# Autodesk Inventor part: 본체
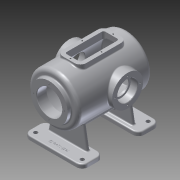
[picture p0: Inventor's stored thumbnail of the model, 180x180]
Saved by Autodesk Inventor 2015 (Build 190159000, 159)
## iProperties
Created: 2016-02
Part Number: 본체
Material: 알루미늄 6061
Document SubType Name: Modeling
Designer: mduedu
Density: 2.71 g/cm^3
Appearance: 알루미늄 - 평지
Author: mduedu
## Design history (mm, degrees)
sketch "스케치2"
  geometry: L1 (0, 100)-(0, -100); L2 (65, -87.083)-(65, 100); L3 (65, 100)-(0, 100); A1 r 170 centre (0, 70) between (0, -100) and (65, -87.083); 2 further points
  constraints: 6 end point, 2 point on circle, 1 centre point, 1 coincident, 1 horizontal, 1 midpoint, 1 parallel, 1 point on line, 1 vertical
  dimensions: "d3" = 200 distance of L1.start L1.end; "d5" = 130 diameter of L2 L1; "d6" = 170 radius of A1
revolve "회전1" sketch "스케치2" stored, may be unused: angle "d7" = 90 deg
sketch "스케치3"
  geometry: C1 r 47.5 at (0, 0); 1 further point
  constraints: 1 centre point, 1 coincident
  dimensions: "d8" = 95 diameter of C1
extrude "돌출2" join sketch "스케치3" distance "d10" = 10; taper "d11" = 0 deg
sketch "스케치5"
  geometry: L1 (47.5, 110)-(47.5, 100) reference; L2 (47.5, 100)-(65, 100) reference; L3 (65, 100)-(65, -87.083) reference; L4 (-65, -87.083)-(-65, 100) reference; L5 (-65, 100)-(-47.5, 100) reference; L6 (-47.5, 100)-(-47.5, 110) reference; L7 (-47.5, 110)-(47.5, 110) reference; L8 (55, 85)-(55, -80.25); L9 (0, 85)-(55, 85); L10 (0, 85)-(0, -90); A1 r 170 centre (0, 70) between (-65, -87.083) and (0, -100) reference; A2 r 170 centre (0, 70) between (0, -100) and (65, -87.083) reference; A3 r 160 centre (0, 70) between (0, -90) and (55, -80.25); 1 further point
  constraints: 6 end point, 2 point on circle, 1 centre point, 1 parallel, 1 perpendicular, 1 point on line, 1 vertical
  dimensions: "d13" = 10 distance between parallel lines of L3 L8; "d14" = 10 radial gap between concentric circles of A3 A1; "d15" = 15 distance between parallel lines of L9 L2
revolve "회전2" sketch "스케치5" stored, may be unused: angle "d16" = 90 deg
hole "구멍1" diameter "d19" = 65; stored, may be unused: countersink angle "d23" = 90 deg, drill point angle "d25" = 118 deg; dims "d17" = 10, "d18" = 10, "d20" = 6, "d21" = 4, "d22" = 2, "d24" = 8
node "작업 평면1"
sketch "스케치6"
  geometry: L1 (47.5, 110)-(-47.5, 110) reference; C1 r 40 at (0, -17); 1 further point
  constraints: 1 centre point, 1 vertical alignment
  dimensions: "d27" = 80 diameter of C1; "d29" = 127 distance from line of C1.centre L1
extrude "돌출3" join sketch "스케치6" stored distance "d30" = 10; taper "d31" = 0 deg
hole "구멍2" diameter "d34" = 42; stored, may be unused: countersink angle "d38" = 90 deg, drill point angle "d40" = 118 deg; dims "d32" = 10, "d33" = 10, "d35" = 6, "d36" = 52, "d37" = 18, "d39" = 8
sketch "스케치7" dims "d41" = 65
  geometry: C1 r 40 at (0, 0) reference; 3 further points
  constraints: 2 vertical alignment, 1 coincident, 2 other
hole "구멍3" sketch "스케치7" at (0, 32.5) diameter "d43" = 3.242; stored, may be unused: countersink angle "d47" = 90 deg, drill point angle "d49" = 118 deg; dims "d44" = 11, "d45" = 13, "d46" = 18, "d48" = 13
sketch "스케치8" dims "d53" = 80
  geometry: 3 further points
  constraints: 2 vertical alignment, 1 coincident, 2 other
hole "구멍4" sketch "스케치8" at (0, 40) diameter "d56" = 3.242; stored, may be unused: countersink angle "d60" = 90 deg, drill point angle "d62" = 118 deg; dims "d57" = 11, "d58" = 13, "d59" = 18, "d61" = 13
fillet "모깎기1" dims "d66" = 10
fillet "모깎기2" dims "d67" = 3
fillet "모깎기3" dims "d68" = 0.3
chamfer "모따기1" distance "d69" = 1; stored, may be unused: second distance "d70" = 2, angle "d71" = 45 deg
node "작업 평면2"
sketch "스케치9"
  geometry: L1 (75, 100)-(-75, 100); L2 (-75, 100)-(-75, -100); L3 (-75, -100)-(75, -100); L4 (75, -100)-(75, 100); 1 further point
  constraints: 8 end point, 2 parallel, 1 horizontal, 1 perpendicular
  dimensions: "d73" = 200 distance of L3.end L1.start; "d75" = 150 distance of L2.end L3.end; "d76" = 100 distance from line of L1 point (0, 0); "d77" = 75 distance from line of L4 point (0, 0)
extrude "돌출4" join sketch "스케치9" distance "d78" = 10; taper "d79" = 0 deg
sketch "스케치10"
  geometry: L1 (-75, -100)-(75, -100) reference; L2 (75, 100)-(-75, 100) reference; L3 (0, -100)-(0, 100); L4 (-75, 100)-(-75, -100) reference; L5 (75, -100)-(75, 100) reference; L6 (-75, 0)-(75, 0); L7 (-50, -63)-(50, -63); L8 (50, -63)-(50, -55); L9 (50, -55)-(-50, -55); L10 (-50, -55)-(-50, -63); L11 (-50, 63)-(50, 63); L12 (50, 63)-(50, 55); L13 (50, 55)-(-50, 55); L14 (-50, 55)-(-50, 63); 1 further point
  constraints: 20 end point, 4 midpoint, 4 symmetric about line, 2 parallel, 1 horizontal, 1 perpendicular, 1 other
  dimensions: "d80" = 8 distance of L9.end L7.start; "d82" = 100 distance of L7.start L7.end; "d83" = 55 distance between parallel lines of L9 L6
extrude "돌출5" join sketch "스케치10" stored distance "d84" = 10; taper "d85" = 0 deg
feature "면 기울기1" dims angle "d86" = 10 deg
sketch "스케치11"
  geometry: L1 (-110, 55)-(-51.482, 55) reference; L2 (-110, -55)-(-51.482, -55) reference; L3 (-95, 55)-(-95, -55); L4 (-65, 90)-(-65, -80.25) reference; 1 further point
  constraints: 2 end point, 2 point on line, 1 perpendicular
  dimensions: "d87" = 30 distance between parallel lines of L3 L4
feature "리브1" sketch "스케치11" dims "d88" = 1, "d89" = 8, "d90" = 0, "d91" = 0, "d92" = 1, "d93" = 1
sketch "스케치12"
  geometry: L1 (-110, 55)-(-51.482, 55) reference; L2 (-110, -55)-(-51.482, -55) reference; L3 (-110, 100)-(-110, -100) reference; L4 (-120, 152)-(-120, -142) reference; L5 (-110, 45)-(-120, 45); L6 (-120, 45)-(-120, -45); L7 (-120, -45)-(-110, -45); L8 (-110, -45)-(-110, 45); 1 further point
  constraints: 8 end point, 2 parallel, 2 point on line, 1 horizontal, 1 perpendicular
  dimensions: "d94" = 10 distance between parallel lines of L7 L2; "d95" = 10 distance between parallel lines of L1 L5
extrude "돌출6" cut sketch "스케치12" stored distance "d96" = 10; taper "d97" = 0 deg
fillet "모깎기4" dims "d98" = 15
sketch "스케치13"
  geometry: C1 r 5 at (-60, -85); C2 r 5 at (60, -85); C3 r 5 at (60, 85); C4 r 5 at (-60, 85); A1 r 15 centre (-60, -85) between (-75, -85) and (-60, -100) reference; A2 r 15 centre (60, -85) between (60, -100) and (75, -85) reference; A3 r 15 centre (60, 85) between (75, 85) and (60, 100) reference; A4 r 15 centre (-60, 85) between (-60, 100) and (-75, 85) reference; 1 further point
  constraints: 4 centre point, 4 coincident, 3 equal radius
  dimensions: "d99" = 10 diameter of C1
extrude "돌출7" cut sketch "스케치13" stored distance "d101" = 10; taper "d102" = 0 deg
fillet "모깎기5" dims "d103" = 3, "d104" = 3
fillet "모깎기6" dims "d105" = 3
sketch "스케치14"
  geometry: L1 (-60, -100)-(60, -100) reference; 2 further points
  constraints: 1 vertical alignment, 1 other
  dimensions: "d106" = 15 distance from line of point (0, -85) L1
feature "엠보싱1" sketch "스케치14" dims "d3" = 200, "d5" = 130, "d6" = 170, "d14" = 10, "d107" = 0.5, "d108" = 0
node "작업 평면3"
sketch "스케치15"
  geometry: L1 (-30, 60)-(30, 60); L2 (30, 60)-(30, -60); L3 (30, -60)-(-30, -60); L4 (-30, -60)-(-30, 60); 2 further points
  constraints: 8 end point, 2 parallel, 1 horizontal, 1 midpoint, 1 perpendicular, 1 vertical alignment
  dimensions: "d110" = 60 distance of L2.end L3.end; "d112" = 60 distance from line of L3 point (0, 0); "d113" = 120 distance of L1.end L2.end
extrude "돌출8" join sketch "스케치15" stored distance "d114" = 10; taper "d115" = 0 deg
fillet "모깎기7" dims "d116" = 15
sketch "스케치16"
  geometry: L1 (-30, -45)-(-30, 45) reference; L2 (-15, 60)-(15, 60) reference; L3 (30, 45)-(30, -45) reference; L4 (15, -60)-(-15, -60) reference; L5 (15, 50)-(-15, 50); L6 (-20, 45)-(-20, -45); L7 (-15, -50)-(15, -50); L8 (20, -45)-(20, 45); A1 r 15 centre (-15, -45) between (-30, -45) and (-15, -60) reference; A2 r 15 centre (-15, 45) between (-15, 60) and (-30, 45) reference; A3 r 15 centre (15, 45) between (30, 45) and (15, 60) reference; A4 r 15 centre (15, -45) between (15, -60) and (30, -45) reference; A5 r 5 centre (-15, 45) between (-15, 50) and (-20, 45); A6 r 5 centre (-15, -45) between (-20, -45) and (-15, -50); A7 r 5 centre (15, -45) between (15, -50) and (20, -45); A8 r 5 centre (15, 45) between (20, 45) and (15, 50); 1 further point
  constraints: 8 end point, 8 point on circle, 4 centre point, 7 other
  dimensions: "d117" = 10 distance between parallel lines of L6 L1
extrude "돌출9" cut sketch "스케치16" stored distance "d118" = 10; taper "d119" = 0 deg
fillet "모깎기8" dims "d120" = 3
sketch "스케치17"
  geometry: L1 (-30, -45)-(-30, 45) reference; L2 (-15, 60)-(15, 60) reference; L3 (30, 45)-(30, -45) reference; L4 (15, -60)-(-15, -60) reference; L5 (20, -45)-(20, 45) reference; L6 (15, 50)-(-15, 50) reference; L7 (-20, 45)-(-20, -45) reference; L8 (-15, -50)-(15, -50) reference; L9 (15, 55)-(-15, 55); L10 (-25, 45)-(-25, -45); L11 (-15, -55)-(15, -55); L12 (25, -45)-(25, 45); A1 r 15 centre (-15, 45) between (-15, 60) and (-30, 45) reference; A2 r 15 centre (15, 45) between (30, 45) and (15, 60) reference; A3 r 15 centre (15, -45) between (15, -60) and (30, -45) reference; A4 r 15 centre (-15, -45) between (-30, -45) and (-15, -60) reference; A5 r 5 centre (15, -45) between (15, -50) and (20, -45) reference; A6 r 5 centre (15, 45) between (20, 45) and (15, 50) reference; A7 r 5 centre (-15, 45) between (-15, 50) and (-20, 45) reference; A8 r 5 centre (-15, -45) between (-20, -45) and (-15, -50) reference; A9 r 10 centre (-15, 45) between (-15, 55) and (-25, 45); A10 r 10 centre (-15, -45) between (-25, -45) and (-15, -55); A11 r 10 centre (15, -45) between (15, -55) and (25, -45); A12 r 10 centre (15, 45) between (25, 45) and (15, 55); 5 further points
  constraints: 8 end point, 8 point on circle, 4 centre point, 4 midpoint, 7 other
  dimensions: "d121" = 5 distance between parallel lines of L10 L1
hole "구멍5" sketch "스케치17" at (0, 55), (25, 0), (0, -55), (-25, 0) diameter "d122" = 3.242; stored, may be unused: countersink angle "d126" = 90 deg, drill point angle "d128" = 118 deg; dims "d123" = 9, "d124" = 13, "d125" = 18, "d127" = 11
fillet "모깎기9" dims "d129" = 3
node "솔리드2"
pattern_circular "원형 패턴1" dims angle "d51" = 360 deg
mirror "대칭1"
pattern_circular "원형 패턴2" dims angle "d64" = 360 deg
node "절단 모서리 투영1"
node "절단 모서리 투영2"
node "절단 모서리 투영3"
other parameters: "d26" = 75
